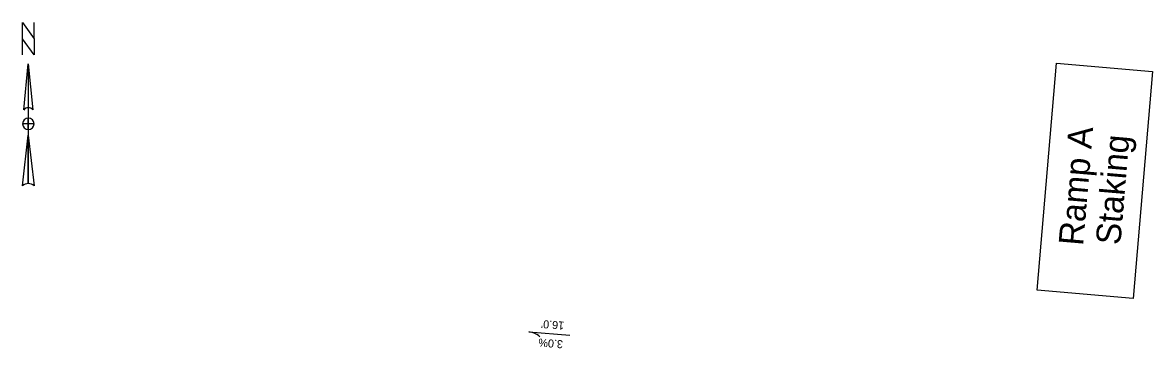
# Model space of a CAD drawing. Extents: x 20506035 to 20507470, y 7969245 to 7972296.
# Drawn here: x 20506422.9 to 20506796.8, y 7972188.2 to 7972295.9 of the extents above; entities that cross this region are included whole.
import ezdxf

# ---------------------------------------------------------------- set-up
doc = ezdxf.new("R2010")
doc.units = 0
doc.layers.add('_CIVIL_CONSTRUCTION', color=7, linetype='Continuous')
doc.layers.add('EdgeShoulder', color=7, linetype='Continuous')

msp = doc.modelspace()

# ---------------------------------------------------------------- linework, layer by layer
at = {"layer": '_CIVIL_CONSTRUCTION'}
msp.add_line((20506590.41, 7972193.64), (20506604.02, 7972192.56), dxfattribs=at)
for points in [[(20506796.82, 7972279.74), (20506790.41, 7972204.7), (20506758.73, 7972207.41), (20506765.13, 7972282.45)], [(20506758.73, 7972207.41), (20506765.13, 7972282.45), (20506796.82, 7972279.74), (20506790.41, 7972204.7)]]:
    msp.add_lwpolyline(points, close=True, dxfattribs=at)
msp.add_arc((20506589.92, 7972187.5), 6.16, 47.2859, 85.4366, dxfattribs=at)
at = {"layer": 'EdgeShoulder'}
for p, q in [((20506424.8, 7972282.23), (20506426.33, 7972267.02)), ((20506424.8, 7972282.23), (20506424.8, 7972242.68)), ((20506423.28, 7972267.02), (20506423.28, 7972267.02)), ((20506423.34, 7972267.16), (20506423.63, 7972267.47)), ((20506424.8, 7972260.55), (20506424.8, 7972260.55)), ((20506422.9, 7972241.92), (20506424.8, 7972258.65))]:
    msp.add_line(p, q, dxfattribs=at)
msp.add_lwpolyline([(20506426.71, 7972285.27), (20506422.9, 7972290.6), (20506422.9, 7972295.92), (20506426.71, 7972290.6)], close=True, dxfattribs=at)
for points in [[(20506422.9, 7972285.27), (20506422.9, 7972295.92), (20506426.71, 7972290.6), (20506426.71, 7972295.92)], [(20506423.28, 7972267.02), (20506424.8, 7972282.23), (20506424.8, 7972267.78)], [(20506426.71, 7972262.45), (20506424.8, 7972262.45), (20506424.8, 7972264.35)], [(20506424.8, 7972260.55), (20506424.8, 7972262.45), (20506422.9, 7972262.45)], [(20506424.8, 7972242.68), (20506424.8, 7972258.65), (20506426.71, 7972241.92)]]:
    msp.add_lwpolyline(points, dxfattribs=at)
for centre, radius, start, end in [((20506424.8, 7972262.45), 1.9, 90, 180), ((20506424.8, 7972265.87), 1.9, 90.0204, 143.1257), ((20506424.8, 7972265.88), 1.9, 36.8481, 90.0218), ((20506424.8, 7972262.45), 1.9, 0, 90), ((20506424.8, 7972262.45), 1.9, 180, 270), ((20506424.8, 7972262.45), 1.9, 270, 360), ((20506424.8, 7972239.92), 2.76, 89.9894, 133.619), ((20506424.8, 7972239.92), 2.76, 46.4021, 90.0006)]:
    msp.add_arc(centre, radius, start, end, dxfattribs=at)

# ---------------------------------------------------------------- texts
at = {"layer": '_CIVIL_CONSTRUCTION'}
for s, height, rotation, p in [('Ramp A', 8.16, 85.1204, (20506773.88, 7972221.94)), ('Staking', 8.16, 85.1204, (20506786.19, 7972222.21)), ("16.0'", 2.664, 175.5654, (20506602.22, 7972196.98)), ('3.0%', 2.664, 175.5654, (20506601.82, 7972190.81))]:
    msp.add_text(s, height=height, rotation=rotation, dxfattribs=at).set_placement(p)

doc.saveas('drawing.dxf')
